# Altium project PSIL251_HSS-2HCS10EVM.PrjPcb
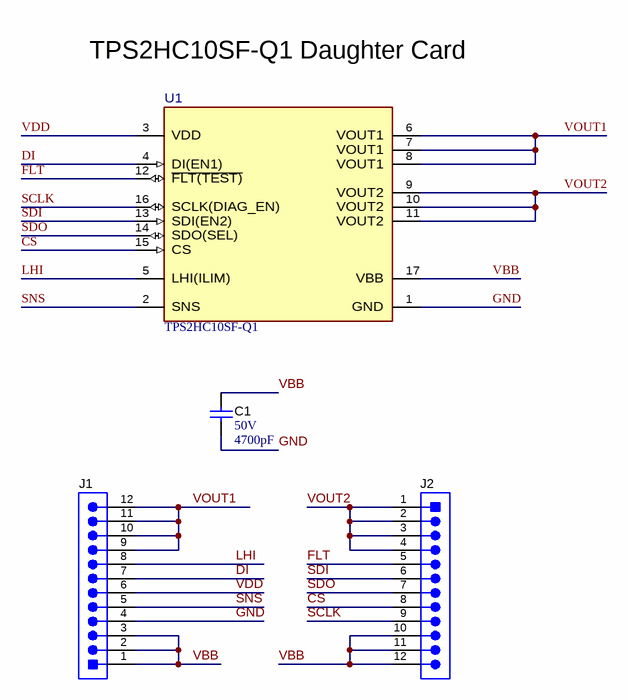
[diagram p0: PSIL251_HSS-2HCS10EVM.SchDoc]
TID: N/A; TechSupport: http://www.ti.com/support; SCH_Rev: A3; PRJ_Title: HSS-2HC10SEVM; PRJ_Number: PSIL251; PRJ_Engineer: Timothy Logan; PRJ_Customer: Public Release; PCB_Rev: A3; PCB_Layout: Timothy Logan; CopyrightYear: 2024
1 sheet, 4 parts. Net scope: global (net labels, ports and power ports of the same name join across sheets).
Board file: PSIL251_HSS-2HCS10EVM.PcbDoc

## Sheet PSIL251_HSS-2HCS10EVM.SchDoc
size Letter; Date: Not shown in title block; ApprovedBy: Not shown in title block; CheckedBy: Not shown in title block; Author: Not shown in title block; CompanyName: Not shown in title block; Engineer: Not shown in title block; Organization: Not shown in title block; Address1: Not shown in title block; Address2: Not shown in title block; Address3: Not shown in title block; Address4: Not shown in title block; DocumentNumber: 2; Revision: Use project parameter SCH_Rev; SheetNumber: 1; SheetTotal: 1; PageSetup: Record=PageOptions¦CenterHorizontal=True¦CenterVertical=True¦PrintScale=1.00¦XCorrection=1.00¦YCorrection=1.00¦PrintKind=0¦BorderSize=5000000¦LeftOffset=0¦BottomOffset=0¦Orientation=2¦PaperLength=1000¦PaperWidth=1000¦Scale=100¦PaperSource=15¦PrintQuality=600¦MediaType=1¦DitherType=10¦PaperKind=Letter¦PrintScaleMode=1

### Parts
C1  VDC_V: 50V  ValueDisplayed: 4700pF  [0805_HV]  (hidden comment: CGA4C2NP01H472J060AA)
J1  800-10-012-10-001000  [Mill-Max_800-10-012-10-001000]  (value not drawn)
J2  800-10-012-10-001000  [Mill-Max_800-10-012-10-001000]  (value not drawn)
U1  TPS2HC10SF-Q1  [PWP0016M-MFG]

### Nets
CS: J2.8 U1.15(CS)
DI: J1.7 U1.4(DI(EN1))
FLT: J2.5 U1.12(~{FLT(TEST)})
GND: C1.2 J1.4 U1.1(GND)
LHI: J1.8 U1.5(LHI(ILIM))
SCLK: J2.9 U1.16(SCLK(DIAG_EN))
SDI: J2.6 U1.13(SDI(EN2))
SDO: J2.7 U1.14(SDO(SEL))
SNS: J1.5 U1.2(SNS)
VBB: C1.1 J1.1 J1.2 J1.3 J2.10 J2.11 J2.12 U1.17(VBB)
VDD: J1.6 U1.3(VDD)
VOUT1: J1.9 J1.10 J1.11 J1.12 U1.6(VOUT1) U1.7(VOUT1) U1.8(VOUT1)
VOUT2: J2.1 J2.2 J2.3 J2.4 U1.9(VOUT2) U1.10(VOUT2) U1.11(VOUT2)

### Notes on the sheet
- TPS2HC10SF-Q1 Daughter Card

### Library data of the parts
C1 = CMP-0080064-1: CAP, CERM, 4700 pF, 50 V,+/- 5%, C0G/NP0, AEC-Q200 Grade 0, 0805; Manufacturer: TDK; TaMin_C: -55°C; Polarized: N; SizeAreaWB_mm2: 6.75; U/M: EA; Value: 4700pF; TaMax_C: 150°C; SizeZ_mm: 1.45; SizeX_mm: 2; SizeY_mm: 1.25; Cap_Case: 0805; SizeArea_mm2: 2.5; AEC Qualified: Y; Cap_F: 4.7nF; AEC Grade: 0; AEC Category: Q200
J1 J2 = CMP-0055083-1: Header, 100mil, 12x1, TH; Manufacturer: Mill-Max; CT: FALSE; CNHeader: TRUE
U1 = CMP-0098232-1: Manufacturer: Texas Instruments; AEC Qualified: No; Standoff Height: 0.05mm; AEC Grade: NA; SizeZ_mm: 1.2mm

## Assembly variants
001: not fitted U1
